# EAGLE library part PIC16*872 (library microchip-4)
MICROCONTROLLER flash type
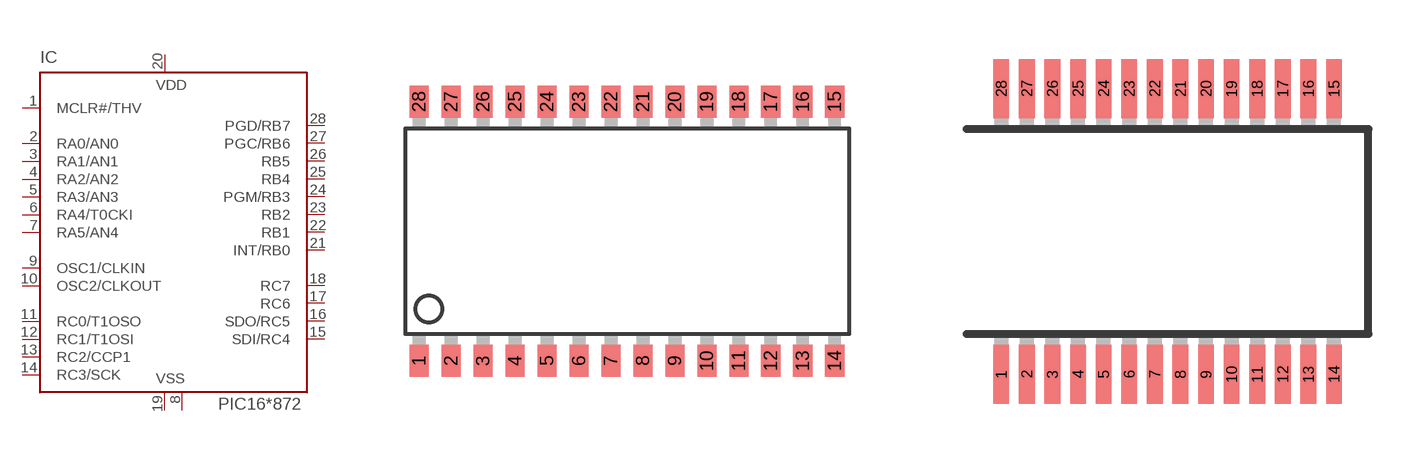
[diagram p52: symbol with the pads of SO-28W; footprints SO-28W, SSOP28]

Designator prefix IC

## PIC16F872SO, PIC16LF872SO  [SO-28W]
1  MCLR#/THV  in
2  RA0/AN0
3  RA1/AN1
4  RA2/AN2
5  RA3/AN3
6  RA4/T0CKI
7  RA5/AN4
8  VSS  pwr
9  OSC1/CLKIN  in
10  OSC2/CLKOUT  out
11  RC0/T1OSO
12  RC1/T1OSI
13  RC2/CCP1
14  RC3/SCK
15  SDI/RC4
16  SDO/RC5
17  RC6
18  RC7
19  VSS  pwr
20  VDD  pwr
21  INT/RB0
22  RB1
23  RB2
24  PGM/RB3
25  RB4
26  RB5
27  PGC/RB6
28  PGD/RB7

## PIC16F872SS, PIC16LF872SS  [SSOP28]
Pads as for SO-28W

## PIC16F872P, PIC16LF872P  [DIL28-3]
Pads as for SO-28W

## Footprint SO-28W (pad centres in mm)
Small Outline Wide Plastic Gull Wing 300-mil body, package type SO
smd 0.762 x 1.27: 1 -7.62,-5.207; 2 -6.35,-5.207; 3 -5.08,-5.207; 4 -3.81,-5.207; 5 -2.54,-5.207; 6 -1.27,-5.207; 7 0,-5.207; 8 1.27,-5.207; 9 2.54,-5.207; 10 3.81,-5.207; 11 5.08,-5.207; 12 6.35,-5.207; 13 7.62,-5.207; 14 8.89,-5.207; 15 8.89,5.08; 16 7.62,5.08; 17 6.35,5.08; 18 5.08,5.08; 19 3.81,5.08; 20 2.54,5.08; 21 1.27,5.08; 22 0,5.08; 23 -1.27,5.08; 24 -2.54,5.08; 25 -3.81,5.08; 26 -5.08,5.08; 27 -6.35,5.08; 28 -7.62,5.08

## Footprint SSOP28 (pad centres in mm)
Shrink Small Outline Package package type SS
smd 0.4 x 1.5: 1 -4.225,-3.625; 2 -3.575,-3.625; 3 -2.925,-3.625; 4 -2.275,-3.625; 5 -1.625,-3.625; 6 -0.975,-3.625; 7 -0.325,-3.625; 8 0.325,-3.625; 9 0.975,-3.625; 10 1.625,-3.625; 11 2.275,-3.625; 12 2.925,-3.625; 13 3.575,-3.625; 14 4.225,-3.625; 15 4.225,3.625; 16 3.575,3.625; 17 2.925,3.625; 18 2.275,3.625; 19 1.625,3.625; 20 0.975,3.625; 21 0.325,3.625; 22 -0.325,3.625; 23 -0.975,3.625; 24 -1.625,3.625; 25 -2.275,3.625; 26 -2.925,3.625; 27 -3.575,3.625; 28 -4.225,3.625

## Footprint DIL28-3 (pad centres in mm)
Dual In Line package type P
drill 0.813 long: 1 -16.51,-3.81; 2 -13.97,-3.81; 3 -11.43,-3.81; 4 -8.89,-3.81; 5 -6.35,-3.81; 6 -3.81,-3.81; 7 -1.27,-3.81; 8 1.27,-3.81; 9 3.81,-3.81; 10 6.35,-3.81; 11 8.89,-3.81; 12 11.43,-3.81; 13 13.97,-3.81; 14 16.51,-3.81; 15 16.51,3.81; 16 13.97,3.81; 17 11.43,3.81; 18 8.89,3.81; 19 6.35,3.81; 20 3.81,3.81; 21 1.27,3.81; 22 -1.27,3.81; 23 -3.81,3.81; 24 -6.35,3.81; 25 -8.89,3.81; 26 -11.43,3.81; 27 -13.97,3.81; 28 -16.51,3.81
